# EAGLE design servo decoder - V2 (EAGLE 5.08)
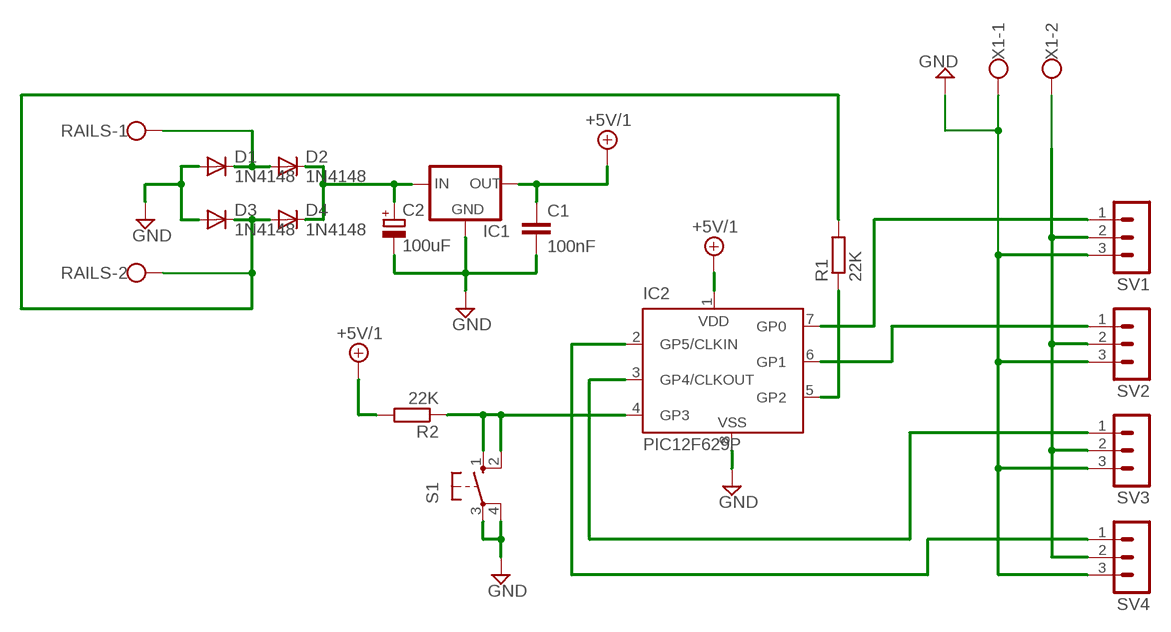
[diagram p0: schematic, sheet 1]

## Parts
C1  100nF  C-EU025-024X044  [C025-024X044]
C2  100uF  CPOL-EUE2.5-5  [E2,5-5]
D1  1N4148  1N4148DO35-10  [DO35-10]
D2  1N4148  1N4148DO35-10  [DO35-10]
D3  1N4148  1N4148DO35-10  [DO35-10]
D4  1N4148  1N4148DO35-10  [DO35-10]
IC1  78XXS  [78XXS]
IC2  PIC12F629P  [DIL8]
R1  22K  R-EU_0207/12  [0207/12]
R2  22K  R-EU_0207/10  [0207/10]
RAILS  W237-102  [W237-102]
S1  10-XX  [B3F-10XX]
SV1  MA03-1  [MA03-1]
SV2  MA03-1  [MA03-1]
SV3  MA03-1  [MA03-1]
SV4  MA03-1  [MA03-1]
X1  W237-102  [W237-102]

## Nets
+5V/1: C1.1 IC1.OUT IC2.1(VDD) R2.2
GND: C1.2 C2.- D1.A D3.A IC1.GND IC2.8(VSS) S1.3(P) S1.4(P1) SV1.3 SV2.3 SV3.3 SV4.3 X1.1
N$1: D1.C D2.A RAILS.1
N$2: D3.C D4.A R1.2 RAILS.2
N$4: C2.+ D2.C D4.C IC1.IN
N$5: IC2.7(GP0) SV1.1
N$6: IC2.6(GP1) SV2.1
N$7: IC2.3(GP4/CLKOUT) SV3.1
N$8: IC2.2(GP5/CLKIN) SV4.1
N$9: IC2.5(GP2) R1.1
N$10: IC2.4(GP3) R2.1 S1.1(S) S1.2(S1)
N$11: SV1.2 SV2.2 SV3.2 SV4.2 X1.2

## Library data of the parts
C1 = rcl:C-EU: CAPACITOR, European symbol
C2 = resistor:CPOL-EU: POLARIZED CAPACITOR, European symbol
D1-D4 = diode:1N4148: DIODE
IC1 = v-reg:78XXS: VOLTAGE REGULATOR
IC2 = microchip:PIC12F6*: Data Sheet 8-Pin FLASH-Based 8-Bit CMOS Microcontrollers Source: http://www.microchip.com .. 41190c.pdf
R1 R2 = rcl:R-EU_: RESISTOR, European symbol
RAILS X1 = con-wago-500:W237-102: WAGO SCREW CLAMP
S1 = switch-omron:10-XX: OMRON SWITCH
SV1-SV4 = con-lstb:MA03-1: PIN HEADER

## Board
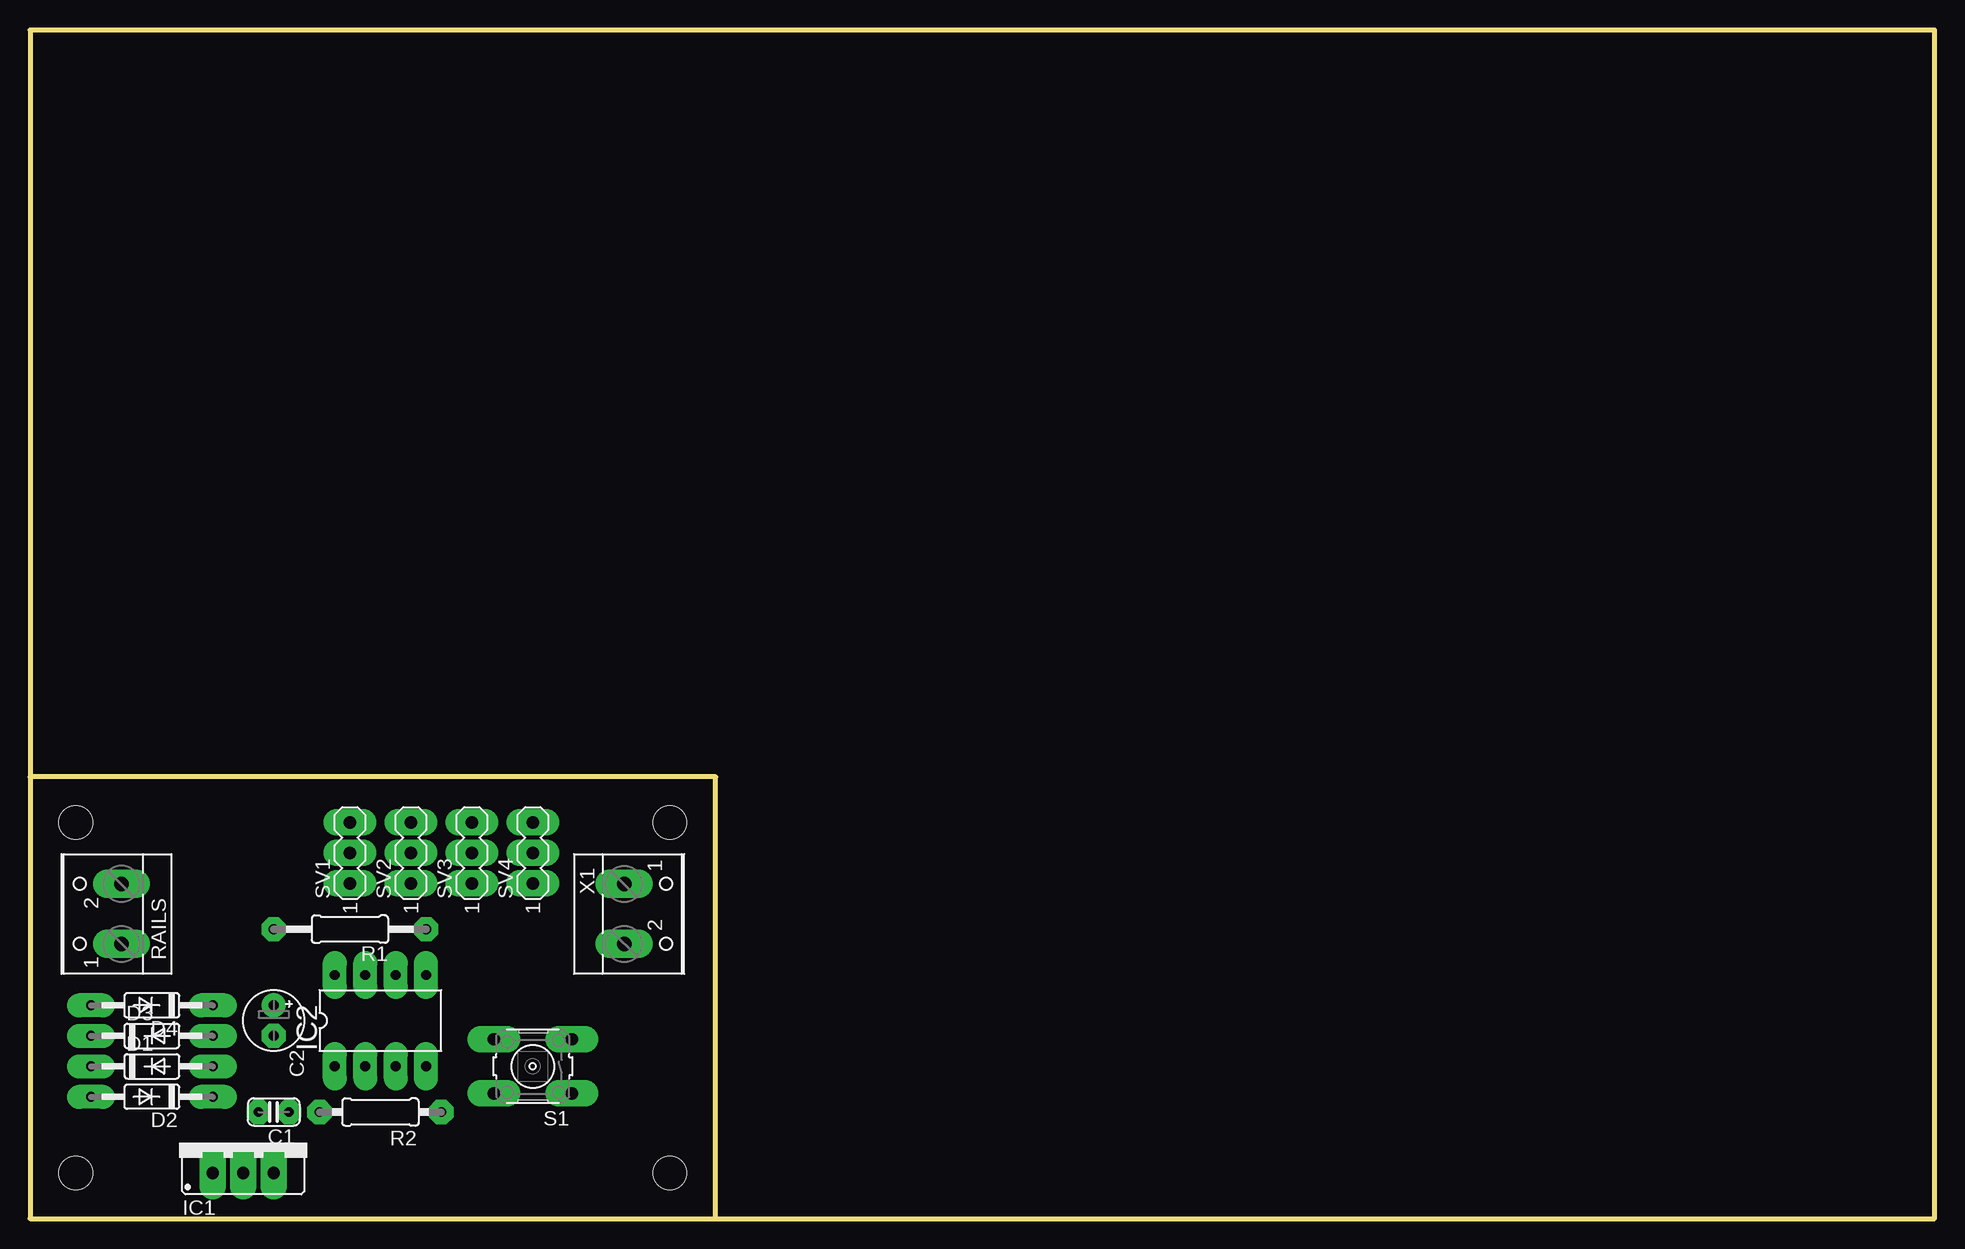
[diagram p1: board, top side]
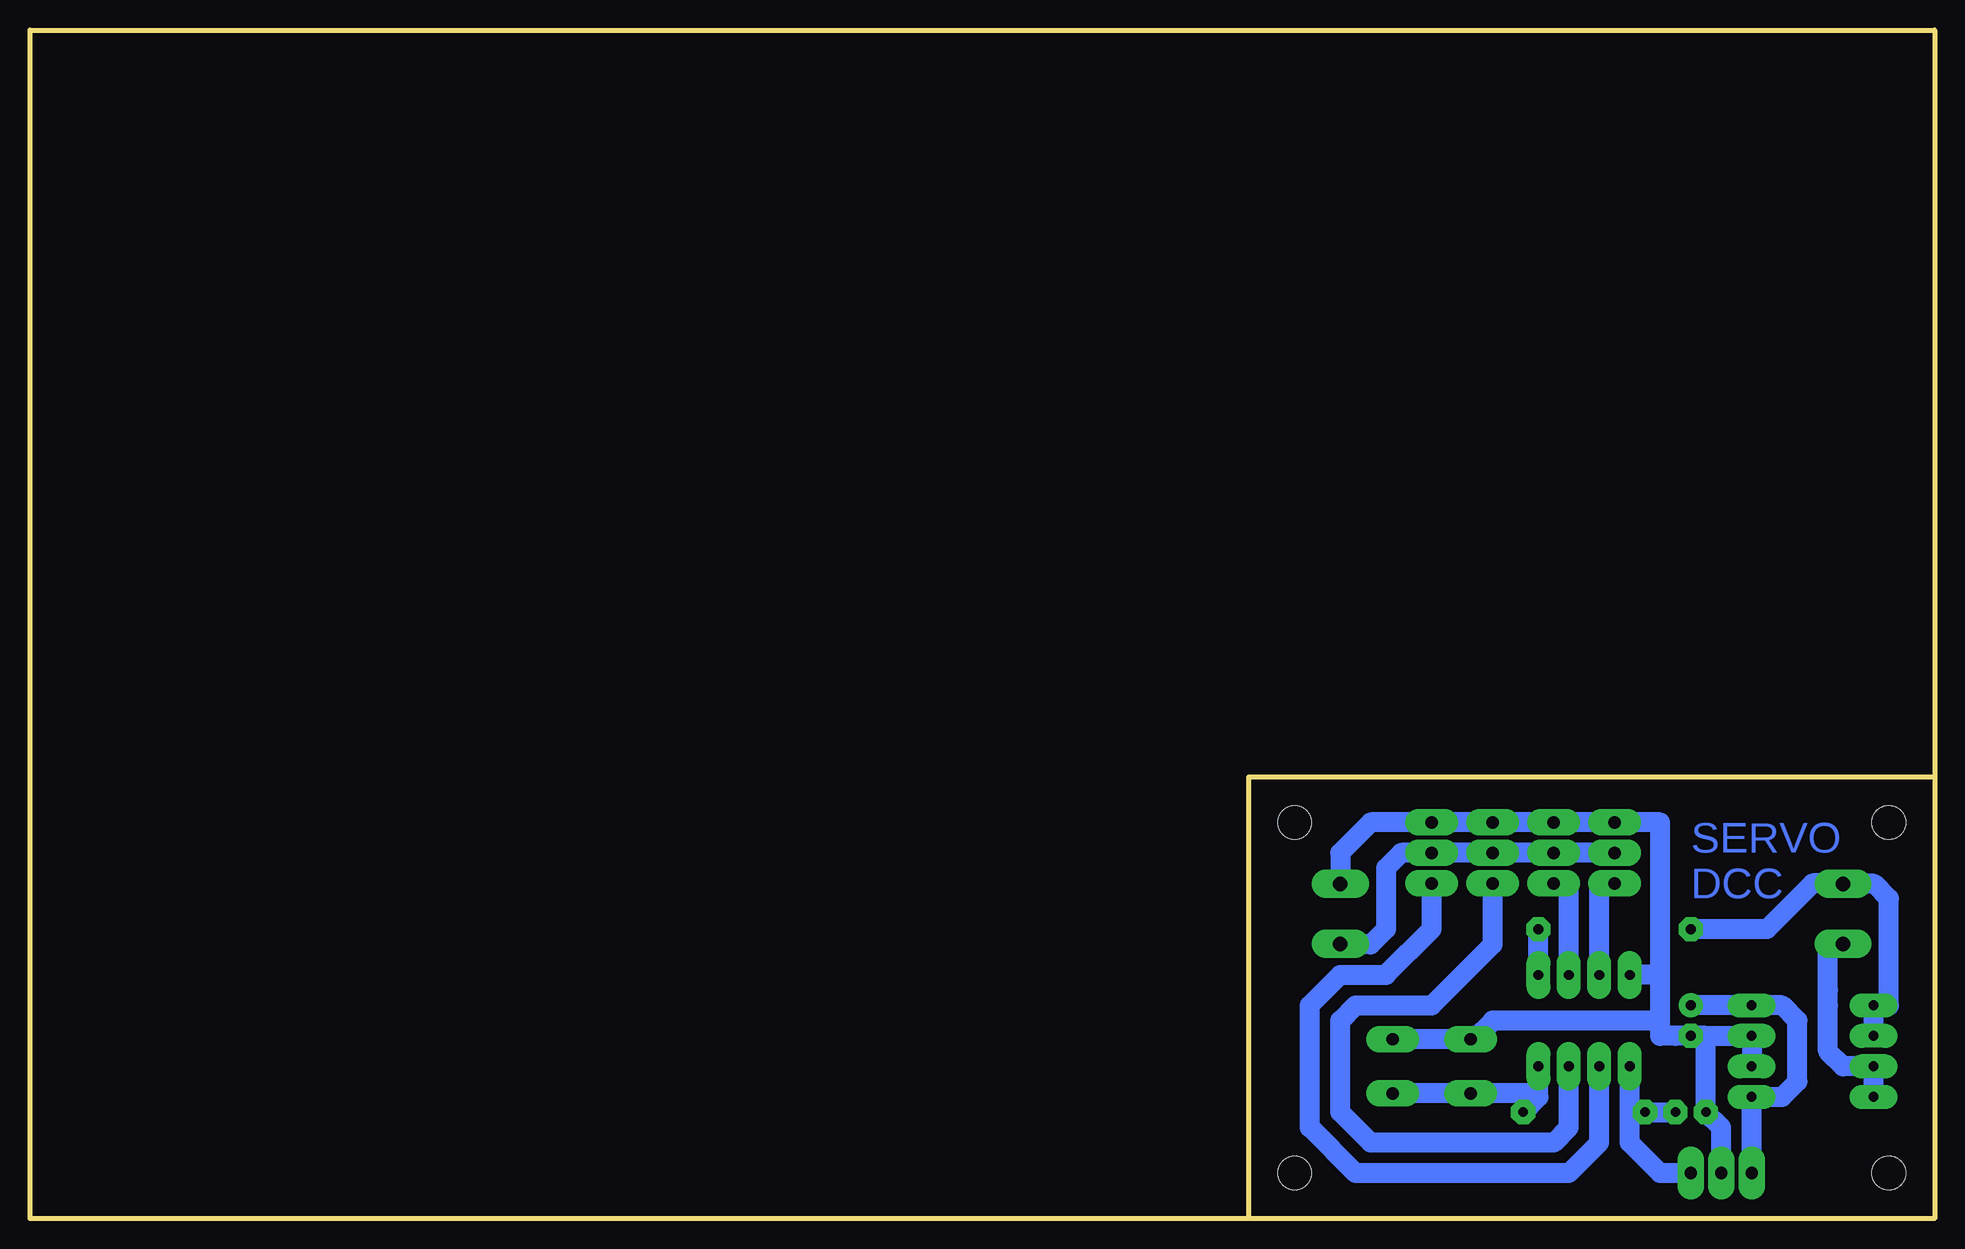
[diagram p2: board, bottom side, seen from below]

Size 158.75 x 99.06 mm. Coordinates in mm from the lower left corner, seen from the top.
Outline: 57.15,0 0,0 0,36.83
Outline: 57.15,0 158.75,0 158.75,99.06 0,99.06 0,36.83
Outline: 57.15,0 57.15,36.83 0,36.83
Copper layers (1*16): Top 1mm / dielectric 1.5mm / Bottom 1mm
Design rules "DRC settings middle": minimum track width 1.2mm, minimum drill 24mil, track to track 0.4mm, track to pad 0.4mm, pad to pad 0.4mm, via to via 0.4mm, smd to smd 8mil, copper to edge 0.5mm, drill to drill 0.5mm, minimum pad ring 0.6mm, minimum via ring 1mm, stop-mask expansion 4mil, vias tented up to drill 0mil, thermal gap 10mil
Holes 2.8 mm at 3.81,33.02 53.34,33.02 53.34,3.81 3.81,3.81

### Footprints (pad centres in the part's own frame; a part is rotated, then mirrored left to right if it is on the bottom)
C025-024X044 = drill 0.813 octagon: 1 -1.27,0; 2 1.27,0
E2,5-5 = drill 0.813 pad 1.6 round: + -1.27,0 | drill 0.813 pad 1.6 octagon: - 1.27,0
DO35-10 = drill 0.813 long: A 5.08,0; C -5.08,0
78XXS = drill 1.016 long: GND 0,-2.54; IN -2.54,-2.54; OUT 2.54,-2.54
DIL8 = drill 0.813 long: 1 -3.81,-3.81; 2 -1.27,-3.81; 3 1.27,-3.81; 4 3.81,-3.81; 5 3.81,3.81; 6 1.27,3.81; 7 -1.27,3.81; 8 -3.81,3.81
0207/12 = drill 0.813 octagon: 1 -6.35,0; 2 6.35,0
0207/10 = drill 0.813 octagon: 1 -5.08,0; 2 5.08,0
W237-102 = drill 1.194 long: 1 -2.5,-1.27; 2 2.5,-1.27
B3F-10XX = drill 1.016 long: 1 -3.251,2.261; 2 3.251,2.261; 3 -3.251,-2.261; 4 3.251,-2.261
MA03-1 = drill 1.016 long: 1 -2.54,0; 2 0,0; 3 2.54,0

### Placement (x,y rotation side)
C1  20.32,8.89 180 top
C2  20.32,16.51 270 top
D1  10.16,12.7 0 top
D2  10.16,10.16 180 top
D3  10.16,15.24 0 top
D4  10.16,17.78 180 top
IC1  17.78,6.35 0 top
IC2  29.21,16.51 0 top
R1  26.67,24.13 180 top
R2  29.21,8.89 180 top
RAILS  6.35,25.4 90 top
S1  41.91,12.7 180 top
SV1  26.67,30.48 90 top
SV2  31.75,30.48 90 top
SV3  36.83,30.48 90 top
SV4  41.91,30.48 90 top
X1  50.8,25.4 270 top

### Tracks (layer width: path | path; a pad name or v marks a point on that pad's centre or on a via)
+5V/1
  Bottom 1.676: IC1.OUT 22.86,3.81 25.4,6.35 25.4,8.89 | 25.4,8.89 IC2.1 | 25.4,8.89 R2.2 C1.1
GND
  Bottom 1.676: D1.A D3.A 19.05,15.24 | 19.05,15.24 C2.- 21.59,15.24 22.86,15.24 22.86,16.51 | IC1.GND 17.78,7.62 C1.2 19.05,15.24 | 22.86,16.51 22.86,20.32 | 22.86,20.32 22.86,33.02 SV1.3 SV2.3 SV3.3 SV4.3 46.99,33.02 49.53,30.48 X1.1 | 22.86,16.51 36.83,16.51 38.38,14.96 S1.4 S1.3 | 22.86,20.32 IC2.8
N$1
  Bottom 1.676: D2.A D1.C 7.62,12.7 8.89,13.97 8.89,17.78 8.89,19.05 8.89,22.86 7.66,22.86 RAILS.1
N$2
  Bottom 1.676: D3.C D4.A 3.81,17.78 3.81,26.67 5.04,27.9 RAILS.2 8.93,27.94 10.16,27.94 13.97,24.13 R1.2
N$4
  Bottom 1.676: IC1.IN D2.C 12.7,10.16 11.43,11.43 11.43,16.51 12.7,17.78 D4.C C2.+
N$5
  Bottom 1.676: IC2.7 27.94,27.94 SV1.1
N$6
  Bottom 1.676: IC2.6 30.48,27.94 SV2.1
N$7
  Bottom 1.676: IC2.3 30.48,7.62 31.75,6.35 46.99,6.35 49.53,8.89 49.53,16.51 48.26,17.78 41.91,17.78 36.83,22.86 SV3.1
N$8
  Bottom 1.676: IC2.2 27.94,6.35 30.48,3.81 48.26,3.81 52.07,7.62 52.07,17.78 49.53,20.32 45.72,20.32 41.91,24.13 SV4.1
N$9
  Bottom 1.676: IC2.5 R1.1
N$10
  Bottom 1.676: S1.1 S1.2 33.3,10.44 33.02,10.16 | 33.02,10.16 IC2.4 | R2.1 33.02,10.16
N$11
  Bottom 1.676: SV1.2 SV2.2 SV3.2 SV4.2 44.45,30.48 45.72,29.21 45.72,24.13 46.99,22.86 49.49,22.86 X1.2

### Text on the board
Bottom: SERVO | DCC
